(* Logix 5000 project; controller Test vendor 1 type 14 code 92 rev 33.11; software revision 33.00; part 3 of 3 *)

ADD_ON_INSTRUCTION Banner_K50ProTouch_PD_v2   (* revision 2.1, vendor Banner Engineering *)
// Takes the raw SINT information and converts that data into actual information.
VAR_IN_OUT
   Process_Data : Banner_K50ProTouch_PDIO_v2; {required}
END_VAR
VAR_INPUT
   Operation_Mode : SINT; {required}   // Linked from Parameters AOI or entered manually.
   Byte_Swap : BOOL; {required}
END_VAR
VAR
   PDO_Temp : SINT[10]; {access None}
   PDI_Temp : SINT[2]; {access None}
END_VAR

ROUTINE Logic   (* ladder *)
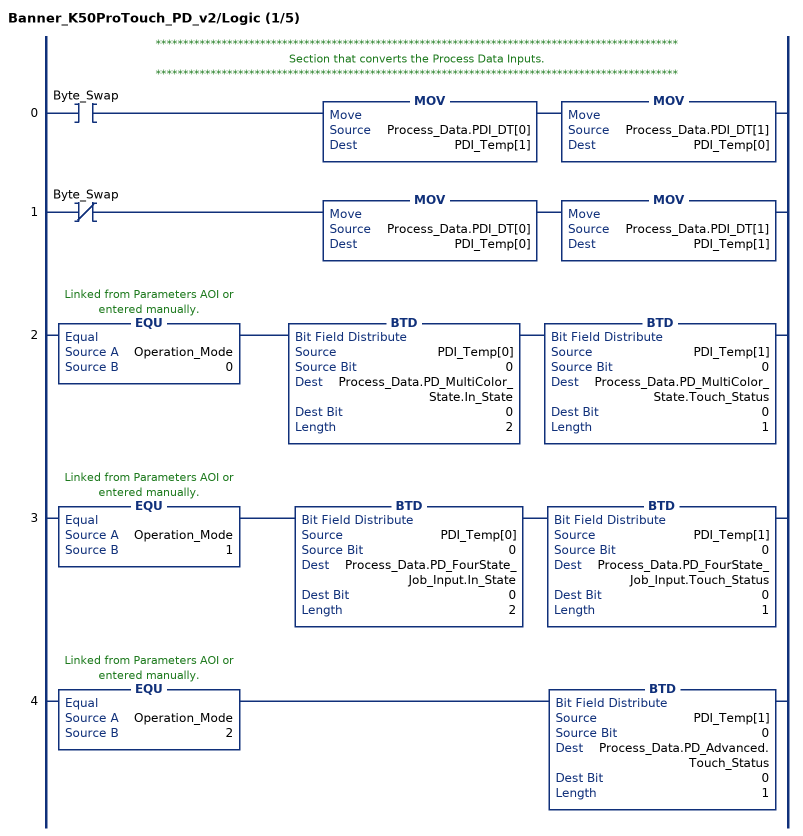
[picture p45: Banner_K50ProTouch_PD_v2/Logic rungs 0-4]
   // ***********************************************************************************************
   // Section that converts the Process Data Inputs.
   // ***********************************************************************************************
   0: XIC(Byte_Swap)MOV(Process_Data.PDI_DT[0],PDI_Temp[1])MOV(Process_Data.PDI_DT[1],PDI_Temp[0]);
   1: XIO(Byte_Swap)MOV(Process_Data.PDI_DT[0],PDI_Temp[0])MOV(Process_Data.PDI_DT[1],PDI_Temp[1]);
   2: EQU(Operation_Mode,0)BTD(PDI_Temp[0],0,Process_Data.PD_MultiColor_State.In_State,0,2)BTD(PDI_Temp[1],0,Process_Data.PD_MultiColor_State.Touch_Status,0,1);
   3: EQU(Operation_Mode,1)BTD(PDI_Temp[0],0,Process_Data.PD_FourState_Job_Input.In_State,0,2)BTD(PDI_Temp[1],0,Process_Data.PD_FourState_Job_Input.Touch_Status,0,1);
   4: EQU(Operation_Mode,2)BTD(PDI_Temp[1],0,Process_Data.PD_Advanced.Touch_Status,0,1);
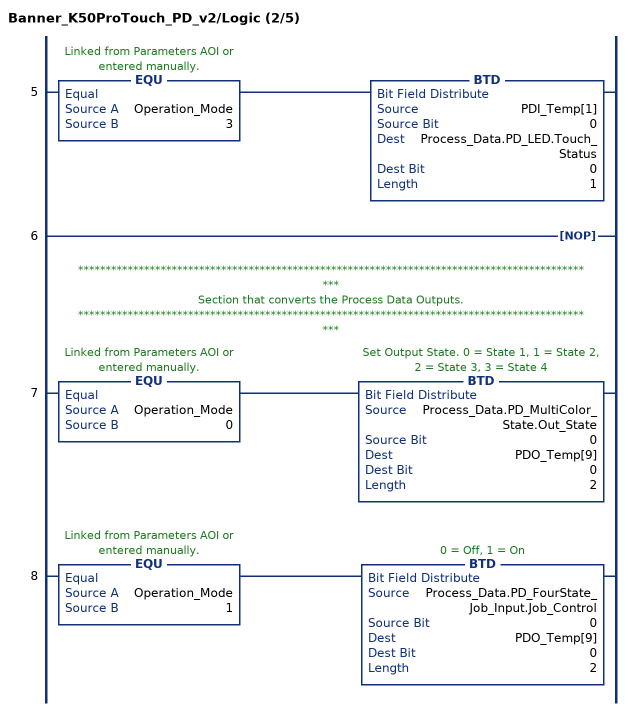
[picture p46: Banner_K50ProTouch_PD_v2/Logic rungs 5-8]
   5: EQU(Operation_Mode,3)BTD(PDI_Temp[1],0,Process_Data.PD_LED.Touch_Status,0,1);
   6: NOP();
   // ***********************************************************************************************
   // Section that converts the Process Data Outputs.
   // ***********************************************************************************************
   7: EQU(Operation_Mode,0)BTD(Process_Data.PD_MultiColor_State.Out_State,0,PDO_Temp[9],0,2);
   8: EQU(Operation_Mode,1)BTD(Process_Data.PD_FourState_Job_Input.Job_Control,0,PDO_Temp[9],0,2);
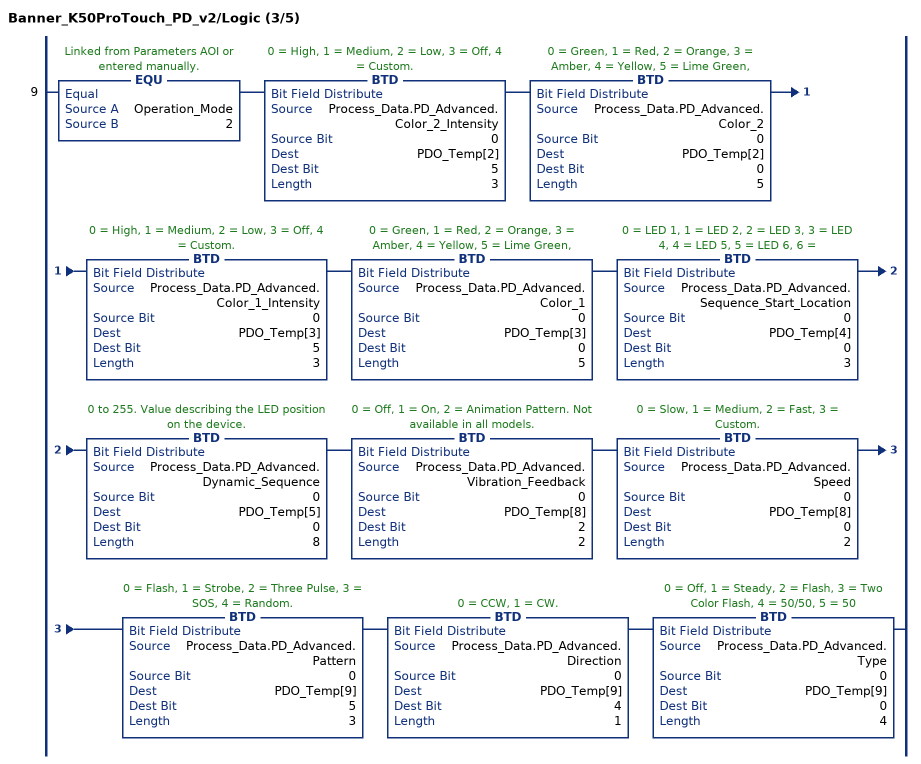
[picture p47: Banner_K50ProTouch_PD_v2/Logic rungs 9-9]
   9: EQU(Operation_Mode,2)BTD(Process_Data.PD_Advanced.Color_2_Intensity,0,PDO_Temp[2],5,3)BTD(Process_Data.PD_Advanced.Color_2,0,PDO_Temp[2],0,5)BTD(Process_Data.PD_Advanced.Color_1_Intensity,0,PDO_Temp[3],5,3)BTD(Process_Data.PD_Advanced.Color_1,0,PDO_Temp[3],0,5)BTD(Process_Data.PD_Advanced.Sequence_Start_Location,0,PDO_Temp[4],0,3)BTD(Process_Data.PD_Advanced.Dynamic_Sequence,0,PDO_Temp[5],0,8)BTD(Process_Data.PD_Advanced.Vibration_Feedback,0,PDO_Temp[8],2,2)BTD(Process_Data.PD_Advanced.Speed,0,PDO_Temp[8],0,2)BTD(Process_Data.PD_Advanced.Pattern,0,PDO_Temp[9],5,3)BTD(Process_Data.PD_Advanced.Direction,0,PDO_Temp[9],4,1)BTD(Process_Data.PD_Advanced.Type,0,PDO_Temp[9],0,4);
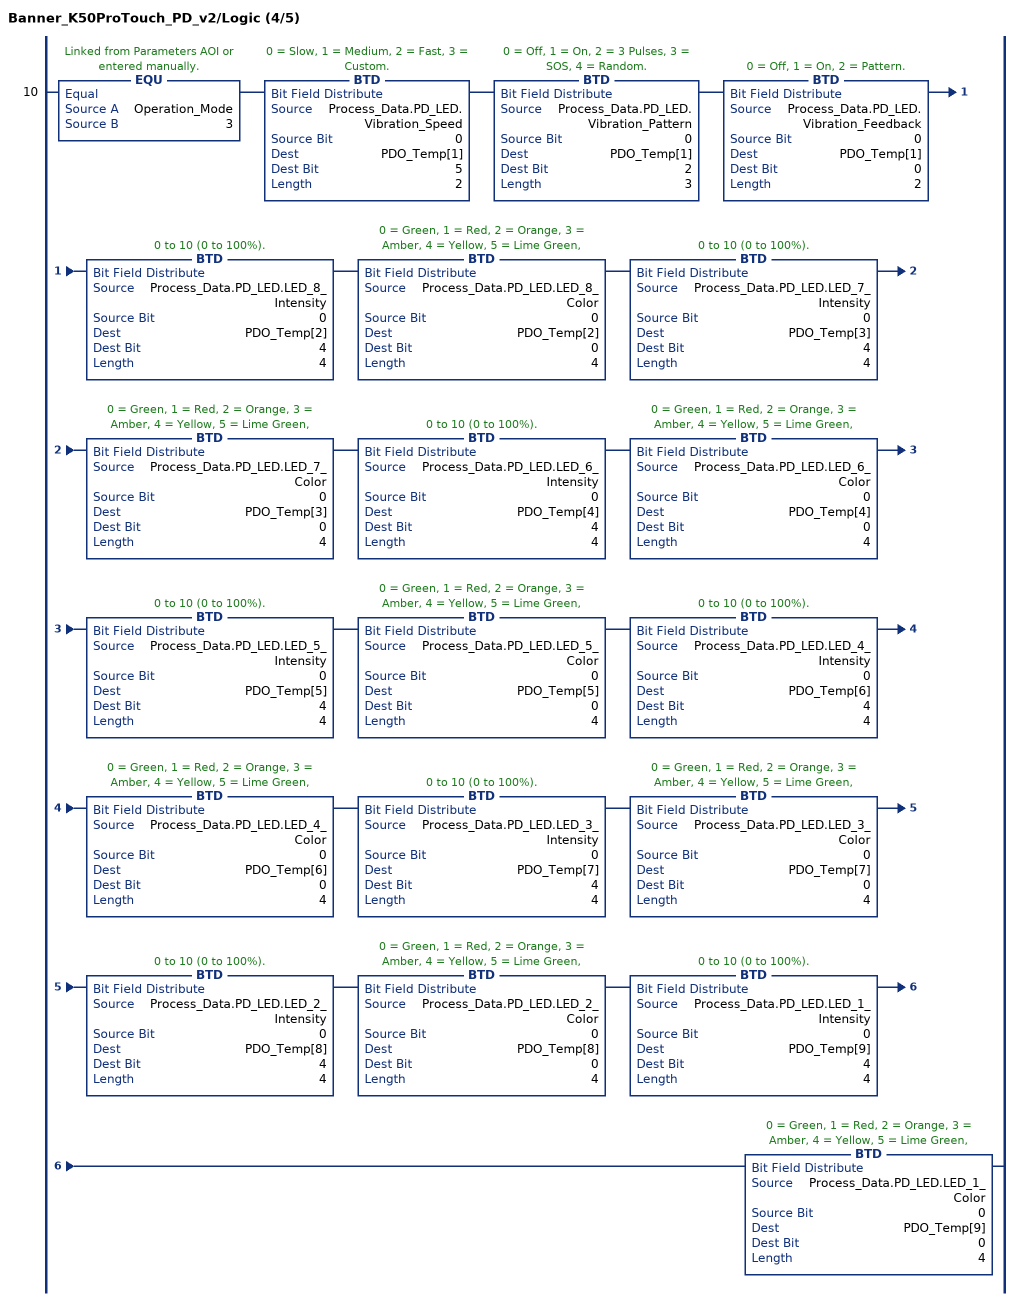
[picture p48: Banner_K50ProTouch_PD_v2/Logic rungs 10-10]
   10: EQU(Operation_Mode,3)BTD(Process_Data.PD_LED.Vibration_Speed,0,PDO_Temp[1],5,2)BTD(Process_Data.PD_LED.Vibration_Pattern,0,PDO_Temp[1],2,3)BTD(Process_Data.PD_LED.Vibration_Feedback,0,PDO_Temp[1],0,2)BTD(Process_Data.PD_LED.LED_8_Intensity,0,PDO_Temp[2],4,4)BTD(Process_Data.PD_LED.LED_8_Color,0,PDO_Temp[2],0,4)BTD(Process_Data.PD_LED.LED_7_Intensity,0,PDO_Temp[3],4,4)BTD(Process_Data.PD_LED.LED_7_Color,0,PDO_Temp[3],0,4)BTD(Process_Data.PD_LED.LED_6_Intensity,0,PDO_Temp[4],4,4)BTD(Process_Data.PD_LED.LED_6_Color,0,PDO_Temp[4],0,4)BTD(Process_Data.PD_LED.LED_5_Intensity,0,PDO_Temp[5],4,4)BTD(Process_Data.PD_LED.LED_5_Color,0,PDO_Temp[5],0,4)BTD(Process_Data.PD_LED.LED_4_Intensity,0,PDO_Temp[6],4,4)BTD(Process_Data.PD_LED.LED_4_Color,0,PDO_Temp[6],0,4)BTD(Process_Data.PD_LED.LED_3_Intensity,0,PDO_Temp[7],4,4)BTD(Process_Data.PD_LED.LED_3_Color,0,PDO_Temp[7],0,4)BTD(Process_Data.PD_LED.LED_2_Intensity,0,PDO_Temp[8],4,4)BTD(Process_Data.PD_LED.LED_2_Color,0,PDO_Temp[8],0,4)BTD(Process_Data.PD_LED.LED_1_Intensity,0,PDO_Temp[9],4,4)BTD(Process_Data.PD_LED.LED_1_Color,0,PDO_Temp[9],0,4);
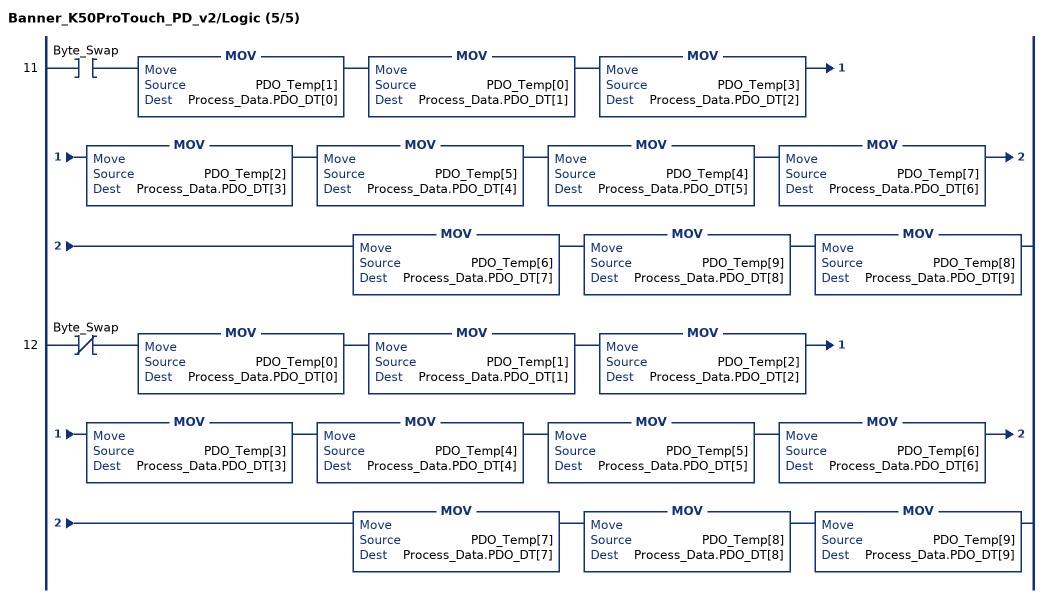
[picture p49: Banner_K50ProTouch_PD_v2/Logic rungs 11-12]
   11: XIC(Byte_Swap)MOV(PDO_Temp[1],Process_Data.PDO_DT[0])MOV(PDO_Temp[0],Process_Data.PDO_DT[1])MOV(PDO_Temp[3],Process_Data.PDO_DT[2])MOV(PDO_Temp[2],Process_Data.PDO_DT[3])MOV(PDO_Temp[5],Process_Data.PDO_DT[4])MOV(PDO_Temp[4],Process_Data.PDO_DT[5])MOV(PDO_Temp[7],Process_Data.PDO_DT[6])MOV(PDO_Temp[6],Process_Data.PDO_DT[7])MOV(PDO_Temp[9],Process_Data.PDO_DT[8])MOV(PDO_Temp[8],Process_Data.PDO_DT[9]);
   12: XIO(Byte_Swap)MOV(PDO_Temp[0],Process_Data.PDO_DT[0])MOV(PDO_Temp[1],Process_Data.PDO_DT[1])MOV(PDO_Temp[2],Process_Data.PDO_DT[2])MOV(PDO_Temp[3],Process_Data.PDO_DT[3])MOV(PDO_Temp[4],Process_Data.PDO_DT[4])MOV(PDO_Temp[5],Process_Data.PDO_DT[5])MOV(PDO_Temp[6],Process_Data.PDO_DT[6])MOV(PDO_Temp[7],Process_Data.PDO_DT[7])MOV(PDO_Temp[8],Process_Data.PDO_DT[8])MOV(PDO_Temp[9],Process_Data.PDO_DT[9]);
END_ROUTINE
END_ADD_ON_INSTRUCTION

VAR_GLOBAL   (* controller tags *)
   IOLM1 : Banner_IOLM_v4;
   IOLM1_Status : Banner_DXMR90_IOLM_v4;
   K50_IOLM1_01 : Banner_K50ProTouch_v2;
   K50_IOLM1_01_PD : Banner_K50ProTouch_PDIO_v2;
   K50_IOLM1_01_PD_Status : Banner_K50ProTouch_PD_v2;
   K50_IOLM1_01_Status : Banner_K50ProTouch_Param_v4;
END_VAR

PROGRAM MainProgram   (* main routine MainRoutine *)

ROUTINE MainRoutine   (* ladder *)
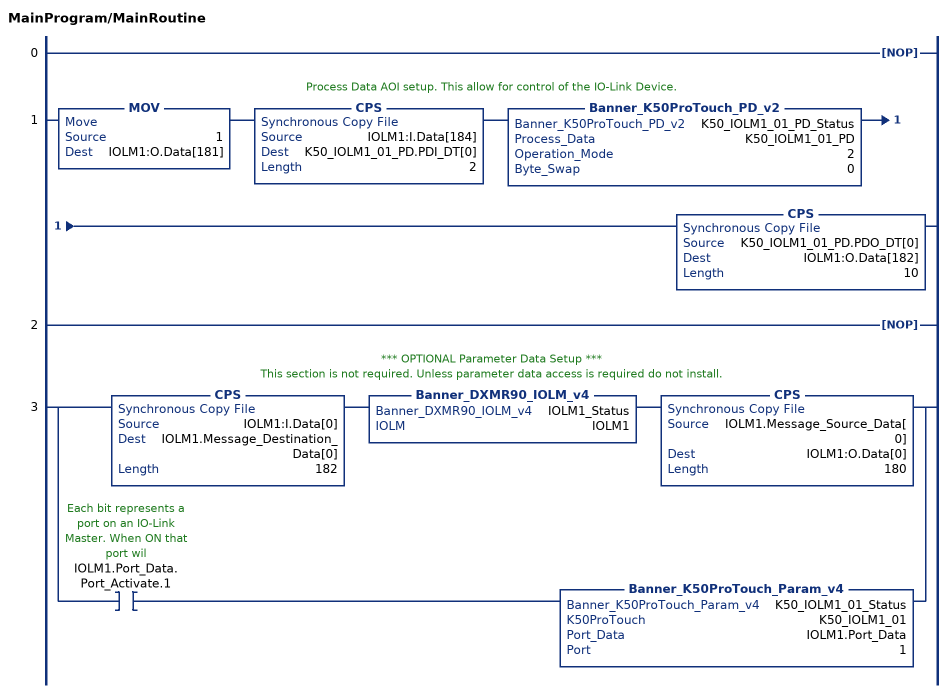
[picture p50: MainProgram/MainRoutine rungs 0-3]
   0: NOP();
   // Process Data AOI setup. This allow for control of the IO-Link Device.
   1: MOV(1,IOLM1:O.Data[181])CPS(IOLM1:I.Data[184],K50_IOLM1_01_PD.PDI_DT[0],2)Banner_K50ProTouch_PD_v2(K50_IOLM1_01_PD_Status,K50_IOLM1_01_PD,2,0)CPS(K50_IOLM1_01_PD.PDO_DT[0],IOLM1:O.Data[182],10);
   2: NOP();
   // *** OPTIONAL Parameter Data Setup ***
   // This section is not required. Unless parameter data access is required do not install.
   3: [CPS(IOLM1:I.Data[0],IOLM1.Message_Destination_Data[0],182) Banner_DXMR90_IOLM_v4(IOLM1_Status,IOLM1) CPS(IOLM1.Message_Source_Data[0],IOLM1:O.Data[0],180) ,XIC(IOLM1.Port_Data.Port_Activate.1) Banner_K50ProTouch_Param_v4(K50_IOLM1_01_Status,K50_IOLM1_01,IOLM1.Port_Data,1) ];
END_ROUTINE
END_PROGRAM
